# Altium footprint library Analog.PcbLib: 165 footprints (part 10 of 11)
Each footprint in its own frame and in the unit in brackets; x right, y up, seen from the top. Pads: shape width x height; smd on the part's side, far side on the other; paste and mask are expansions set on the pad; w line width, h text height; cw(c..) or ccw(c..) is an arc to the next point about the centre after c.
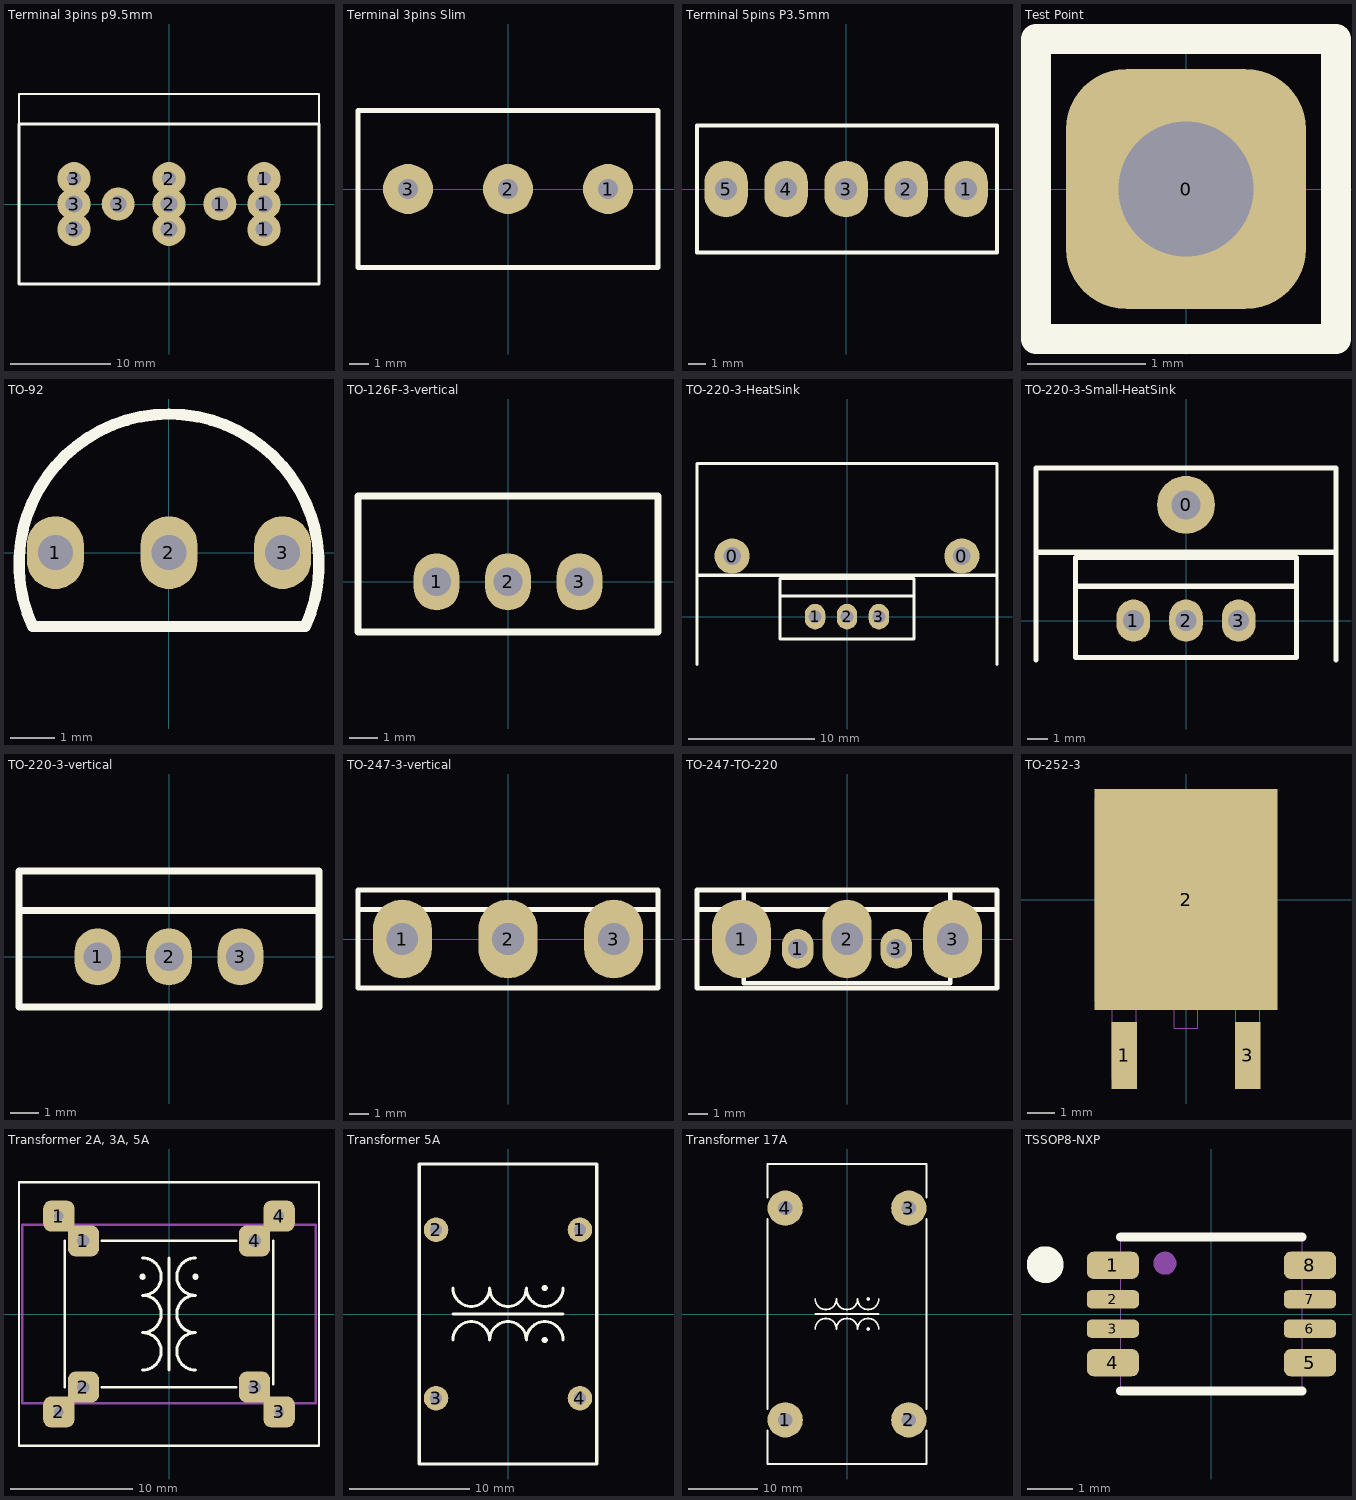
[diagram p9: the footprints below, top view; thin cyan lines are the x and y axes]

## Terminal 3pins p9.5mm [mil]
height 550
pads (11):
  round 130 hole 65: 1(200,0) 1(374.02,-100) 1(374.02,0) 2(0,-100) 2(0,0) 3(-374.02,-100) 3(-374.02,0) 3(-200,0)
  round 130 hole 55: 1(374.02,100) 2(0,100) 3(-374.02,100)
Top Overlay:
  lines w6: -590.55,314.96 -590.55,433.07 590.55,433.07 590.55,314.96
  lines w10: -590.55,-314.96 590.55,-314.96 590.55,314.96 -590.55,314.96 -590.55,-314.96

## Terminal 3pins Slim [mil]
height 400
pads (3):
  round 100 hole 40: 1(200,0) 2(0,0) 3(-200,0)
Top Overlay:
  lines w10: -300,-157.48 300,-157.48 300,157.48 -300,157.48 -300,-157.48

## Terminal 5pins P3.5mm [mil] "XK128L-3.5MM"
height 338.58
pads (5):
  oval 100x130 hole 51: 1(275.59,0) 2(137.8,0) 3(0,0) 4(-137.8,0) 5(-275.59,0)
Top Overlay:
  lines w10: -342.52,-145.67 -342.52,145.67 346.46,145.67 346.46,-145.67 -342.52,-145.67

## Test Point [mil]
pads (1):
  rrect50% 80x80 hole 45: 0(0,0)
Top Overlay:
  lines w10: -50,-50 50,-50 50,50 -50,50 -50,-50
Bottom Overlay:
  lines w10: -50,-50 -50,50 50,50 50,-50 -50,-50

## TO-92 [mil]
height 400
pads (3):
  oval 50x64 hole 31: 1(-100,0) 2(0,0) 3(100,0)
Top Overlay:
  lines w10: -120,-65 cw(c0,-10) 120,-65 -120,-65
Mechanical 13:
  lines w1: -120,-65 cw(c0,-10) 120,-65 -120,-65
  text ".Designator" at -118,-24 h40

## TO-126F-3-vertical [mil]
pads (3):
  oval 64x80 hole 40: 1(-100,0) 2(0,0) 3(100,0)
Top Overlay:
  lines w10: -210,-70 -210,120 210,120 210,-70 -210,-70

## TO-220-3-HeatSink [mil]
pads (5):
  round 110 hole 55: 0(-360,190) 0(360,190)
  oval 64x80 hole 40: 1(-100,0) 2(0,0) 3(100,0)
Top Overlay:
  lines w10: -470,-150 -470,480 470,480 470,-150 ; -470,130 470,130 ; -210,65 210,65 ; -210,-70 210,-70 210,120 -210,120 -210,-70

## TO-220-3-Small-HeatSink [mil]
pads (4):
  round 110 hole 55: 0(0,220)
  oval 64x80 hole 40: 1(-100,0) 2(0,0) 3(100,0)
Top Overlay:
  lines w10: -285,-75 -285,290 285,290 285,-75 ; -285,130 285,130 ; -210,65 210,65 ; -210,-70 210,-70 210,120 -210,120 -210,-70

## TO-220-3-vertical [mil]
pads (3):
  oval 64x80 hole 40: 1(-100,0) 2(0,0) 3(100,0)
Top Overlay:
  lines w10: -210,65 210,65 ; -210,-70 210,-70 210,120 -210,120 -210,-70

## TO-247-3-vertical [mil]
pads (3):
  oval 120x160 hole 65: 1(-215,0) 2(0,0) 3(215,0)
Top Overlay:
  lines w10: -305,60 305,60 ; -305,-100 -305,100 305,100 305,-100 -305,-100

## TO-247-TO-220 [mil]
pads (5):
  oval 120x160 hole 65: 1(-215,0) 3(215,0)
  oval 64x80 hole 40: 1(-100,-19.81) 3(100,-19.81)
  oval 100x160 hole 65: 2(0,0)
Top Overlay:
  lines w10: -305,60 305,60 ; -305,100 -305,-100 305,-100 305,100 ; -305,100 305,100 ; -305,100 305,100 ; -210,-89.81 210,-89.81 210,100.19 -210,100.19 -210,-89.81

## TO-252-3 [mil]
pads (3):
  rect 37x98 smd paste+0 mask+0: 1(-90.16,-227.5) 3(90.16,-227.5)
  rect 267x323 smd paste+0 mask+0: 2(0,0)
Mechanical 13:
  lines w1: -17.5,-147.5 -17.5,-187.5 17.5,-187.5 17.5,-147.5 ; -132.5,-147.5 -132.5,147.5 132.5,147.5 132.5,-147.5 -132.5,-147.5 ; -107.66,-262.5 -72.66,-262.5 -72.66,-147.5 -107.66,-147.5 -107.66,-262.5 ; 72.66,-262.5 107.66,-262.5 107.66,-147.5 72.66,-147.5 72.66,-262.5
  text ".Designator" at -95,-75 h40

## Transformer 2A, 3A, 5A [mm]
height 30
pads (8):
  rrect50% 2.54x2.54 hole 0.8: 1(-9,8) 2(-9,-8) 3(9,-8) 4(9,8)
  rrect50% 2.54x2.54 hole 1.016: 1(-6.985,5.969) 2(-6.985,-5.969) 3(6.985,-5.969) 4(6.985,5.969)
Top Overlay:
  circle w0.254: c-2.159,3.048 r0.127
  circle w0.254: c2.159,3.048 r0.127
  lines w0.2: -8.5,-6 -8.5,6 ; -5.5,-6 5.5,-6 ; -5.5,6 5.5,6 ; 8.5,-5.75 8.5,6 ; -12.25,-10.75 12.25,-10.75 12.25,10.75 -12.25,10.75 -12.25,-10.75
  lines w0.254: -2.159,-4.572 ccw(c-2.159,-3.048) -2.159,-1.524 ccw(c-2.159,0) -2.159,1.524 ccw(c-2.159,3.048) -2.159,4.572 ; 2.159,-4.572 cw(c2.159,-3.048) 2.159,-1.524 cw(c2.159,0) 2.159,1.524 cw(c2.159,3.048) 2.159,4.572 ; 0,-4.572 0,4.572 0,-4.572
Mechanical 13:
  lines w0.2: -12,-7.3 -12,7.3 12,7.3 12,-7.3 -12,-7.3

## Transformer 5A [mil]
pads (4):
  round 80 hole 40: 1(235,275) 2(-235,275) 3(-235,-275) 4(235,-275)
Top Overlay:
  circle w10: c120,-85 r5
  circle w10: c120,85 r5
  lines w10: -180,-85 cw(c-120,-85) -60,-85 cw(c0,-85) 60,-85 cw(c120,-85) 180,-85 ; -180,0 180,0 ; -180,85 ccw(c-120,85) -60,85 ccw(c0,85) 60,85 ccw(c120,85) 180,85 ; -290,-490 290,-490 290,490 -290,490 -290,-490

## Transformer 17A [mil]
height 1650
pads (4):
  round 200 hole 80: 1(-350,-600) 2(350,-600) 3(350,600) 4(-350,600)
Top Overlay:
  circle w10: c120,85 r5
  circle w10: c120,-85 r5
  lines w10: -450,-660 -450,-850 450,-850 450,-660 ; -450,-540 -450,540 ; -450,660 -450,850 450,850 450,660 ; -180,-85 cw(c-120,-85) -60,-85 cw(c0,-85) 60,-85 cw(c120,-85) 180,-85 ; -180,0 180,0 ; -180,85 ccw(c-120,85) -60,85 ccw(c0,85) 60,85 ccw(c120,85) 180,85 ; 450,-540 450,540

## TSSOP8-NXP [mm]
height 1.1
pads (8):
  rrect50% 1.15x0.6 smd paste+0 mask+0.05: 1(-2.175,1.075) 4(-2.175,-1.075) 5(2.175,-1.075) 8(2.175,1.075)
  rrect50% 1.15x0.4 smd paste+0 mask+0.05: 2(-2.175,0.325) 3(-2.175,-0.325) 6(2.175,-0.325) 7(2.175,0.325)
Top Overlay:
  circle w0.406: c-3.668,1.088 r0.203
  lines w0.203: -2,-1.7 2,-1.7 ; -2,1.7 2,1.7
Mechanical 13:
  circle w0.254: c-1.026,1.121 r0.127
  lines w0.025: -2,-1.7 2,-1.7 2,1.7 -2,1.7 -2,-1.7
  text ".Designator" at -0.425,1.225 h1.02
